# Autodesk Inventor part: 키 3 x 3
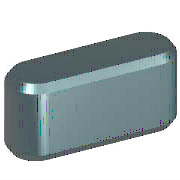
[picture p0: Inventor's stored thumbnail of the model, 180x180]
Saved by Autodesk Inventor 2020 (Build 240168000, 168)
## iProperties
Created: 2012-02
Part Number: 키 3 x 3
Material: 강철, 연강
Description: 키 및 해당 키홈
Document SubType Name: Modeling
Standard: KS B 1311
Designer: mduedu
Standards Organization: KS
Language: ko-KR
Size Designation: 3 x 3 x 12
Categories: <MemberInstance><Categories><Category DisplayName="샤프트 부품" InternalName="7f7aeb1f-a693-4053-b835-cee3144e0d98" Mnemonic="SHFT"><Category DisplayName="키" Interna
Density: 7.86 g/cm^3
Mass: 0.790122 g
Surface Area: 1.42216 cm^2
Volume: 0.100524 cm^3
Appearance: 노란색
IsCustomPart: 1
Author: mduedu
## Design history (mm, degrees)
workplane "Work Plane1"
workplane "Work Plane2"
sketch "스케치1"
  geometry: L1 (1.5, 1.5)-(10.5, 1.5); L2 (10.5, -1.5)-(1.5, -1.5); L3 (0, 9.4)-(0, -7.4) reference; L4 (-5, 0)-(30, 0) reference; L5 (12, 0)-(12, 7); A1 r 1.5 centre (1.5, 0) between (1.5, 1.5) and (1.5, -1.5); A2 r 1.5 centre (10.5, 0) between (10.5, -1.5) and (10.5, 1.5)
  constraints: 6 end point, 5 point on circle, 4 tangent, 3 point on line, 2 centre point, 1 horizontal, 1 parallel, 1 perpendicular
  dimensions: "d0" = 1.5 radius of A1 (= 0.5 x PB); "d13" = 1.5 radius of A2 (= 0.5 x PB); "d14" = 12 distance between parallel lines of L5 L3 (= NLG)
extrude "본체1" new body sketch "스케치1" taper "d3" = 0 deg; stored distance "d4" = 10
workplane "Work Plane3"
body "Solid1"
chamfer "모따기1" distance "d8" = 0.25 (= PHH); stored, may be unused: second distance "d9" = 0.25 (= PHH), angle "d15" = 45 deg
other parameters: "d1" = -1.8 (= -PNT), "d2" = 1.2 (= PH - PNT), "NLG" = 12 [user parameter; used in 3 equation terms], "PB" = 3 [user parameter; used in 2 equation terms], "PNT" = 1.8 [user parameter; used in 2 equation terms], "PH" = 3 [user parameter; used in 1 equation term], "PHH" = 0.25 [user parameter; used in 2 equation terms], "d10" = 0, "d16" = 0, "d17" = 0, "d18" = 0, "WDMIN" = 8 [user parameter], "PLB2" = 12 (= NLG) [user parameter], "PLB1" = 12 (= NLG) [user parameter], "RR" = 0.08 [user parameter], "PUEB" = 1.4 [user parameter]
